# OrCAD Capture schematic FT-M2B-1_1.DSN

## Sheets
1 INDEX: title: 01-INDEX; rev: 1.1
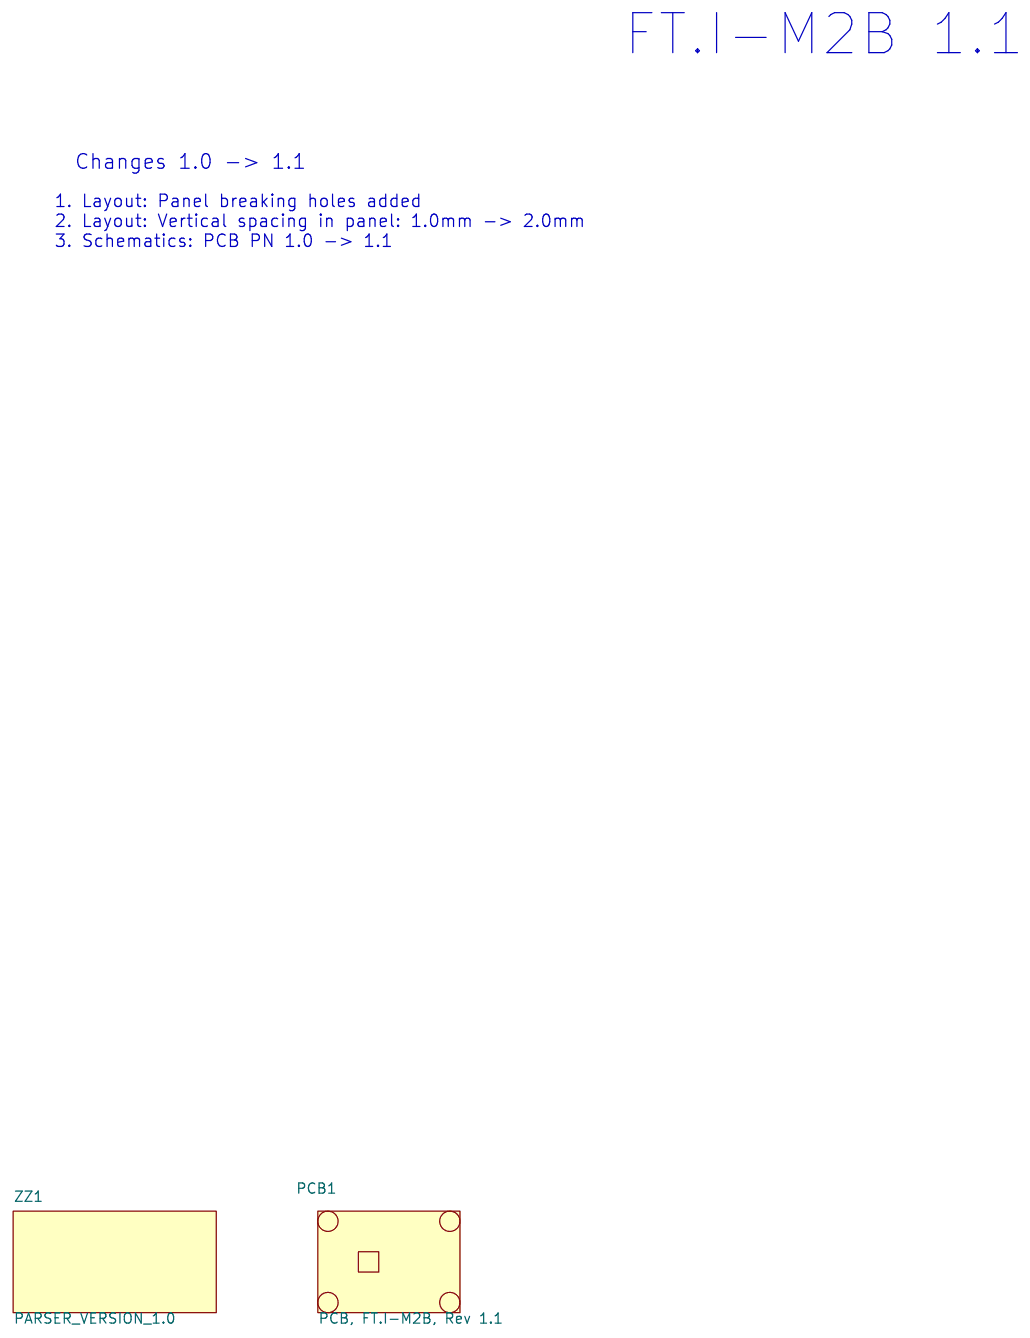
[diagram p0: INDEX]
2 TRIP: size A; title: 02-TRIP
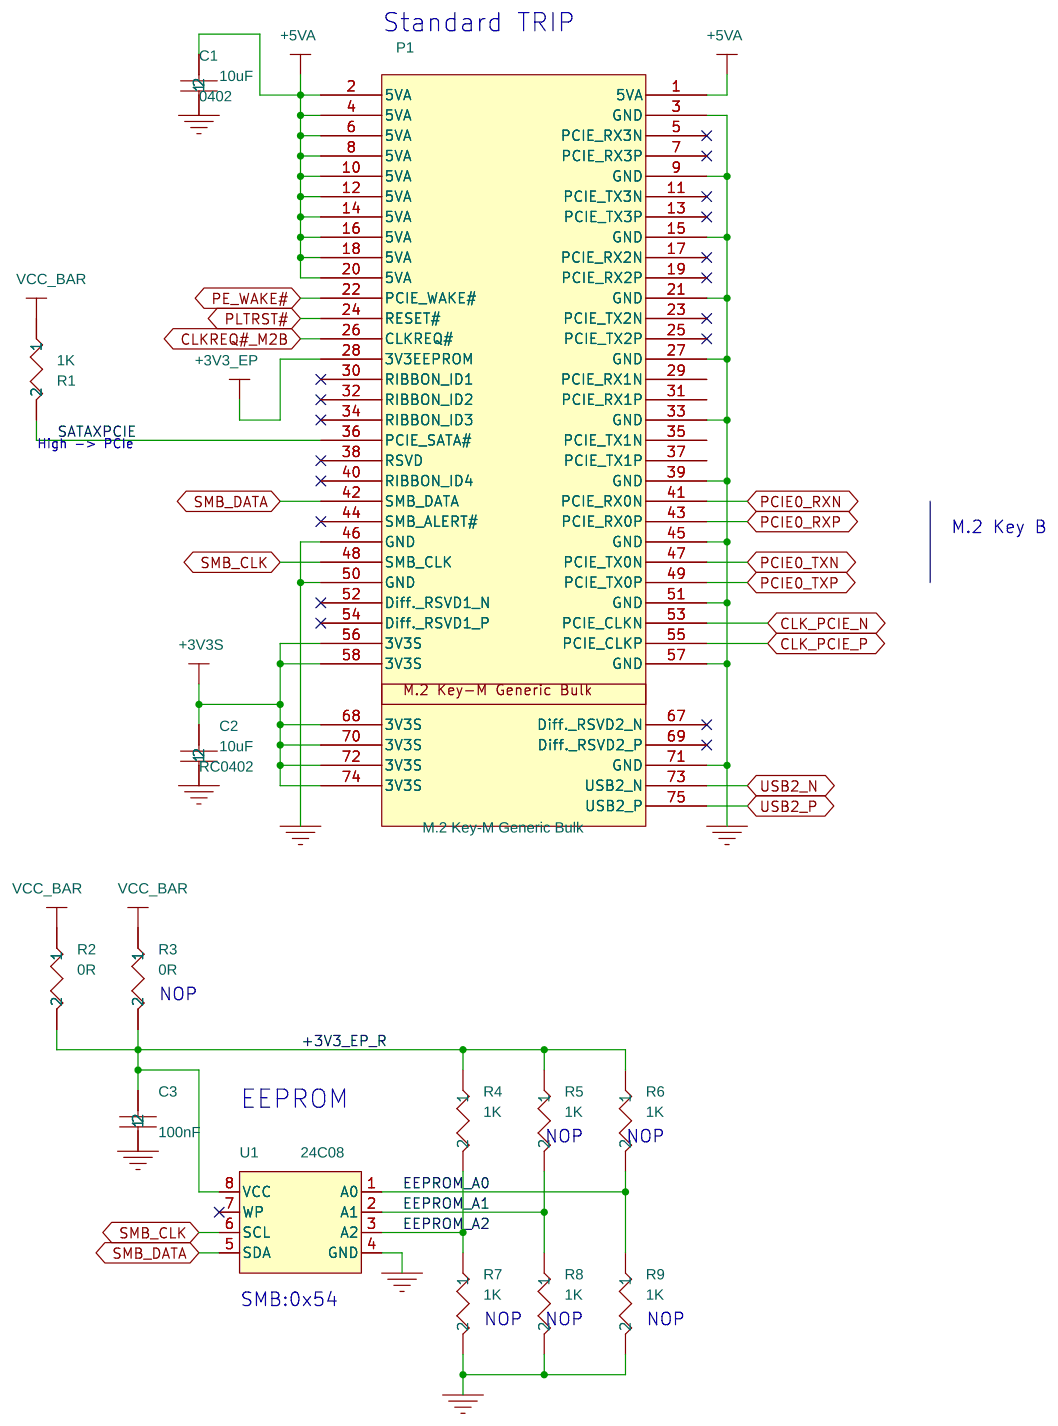
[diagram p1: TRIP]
3 M.2 Key B: size A4; title: 04-M.2 Key B
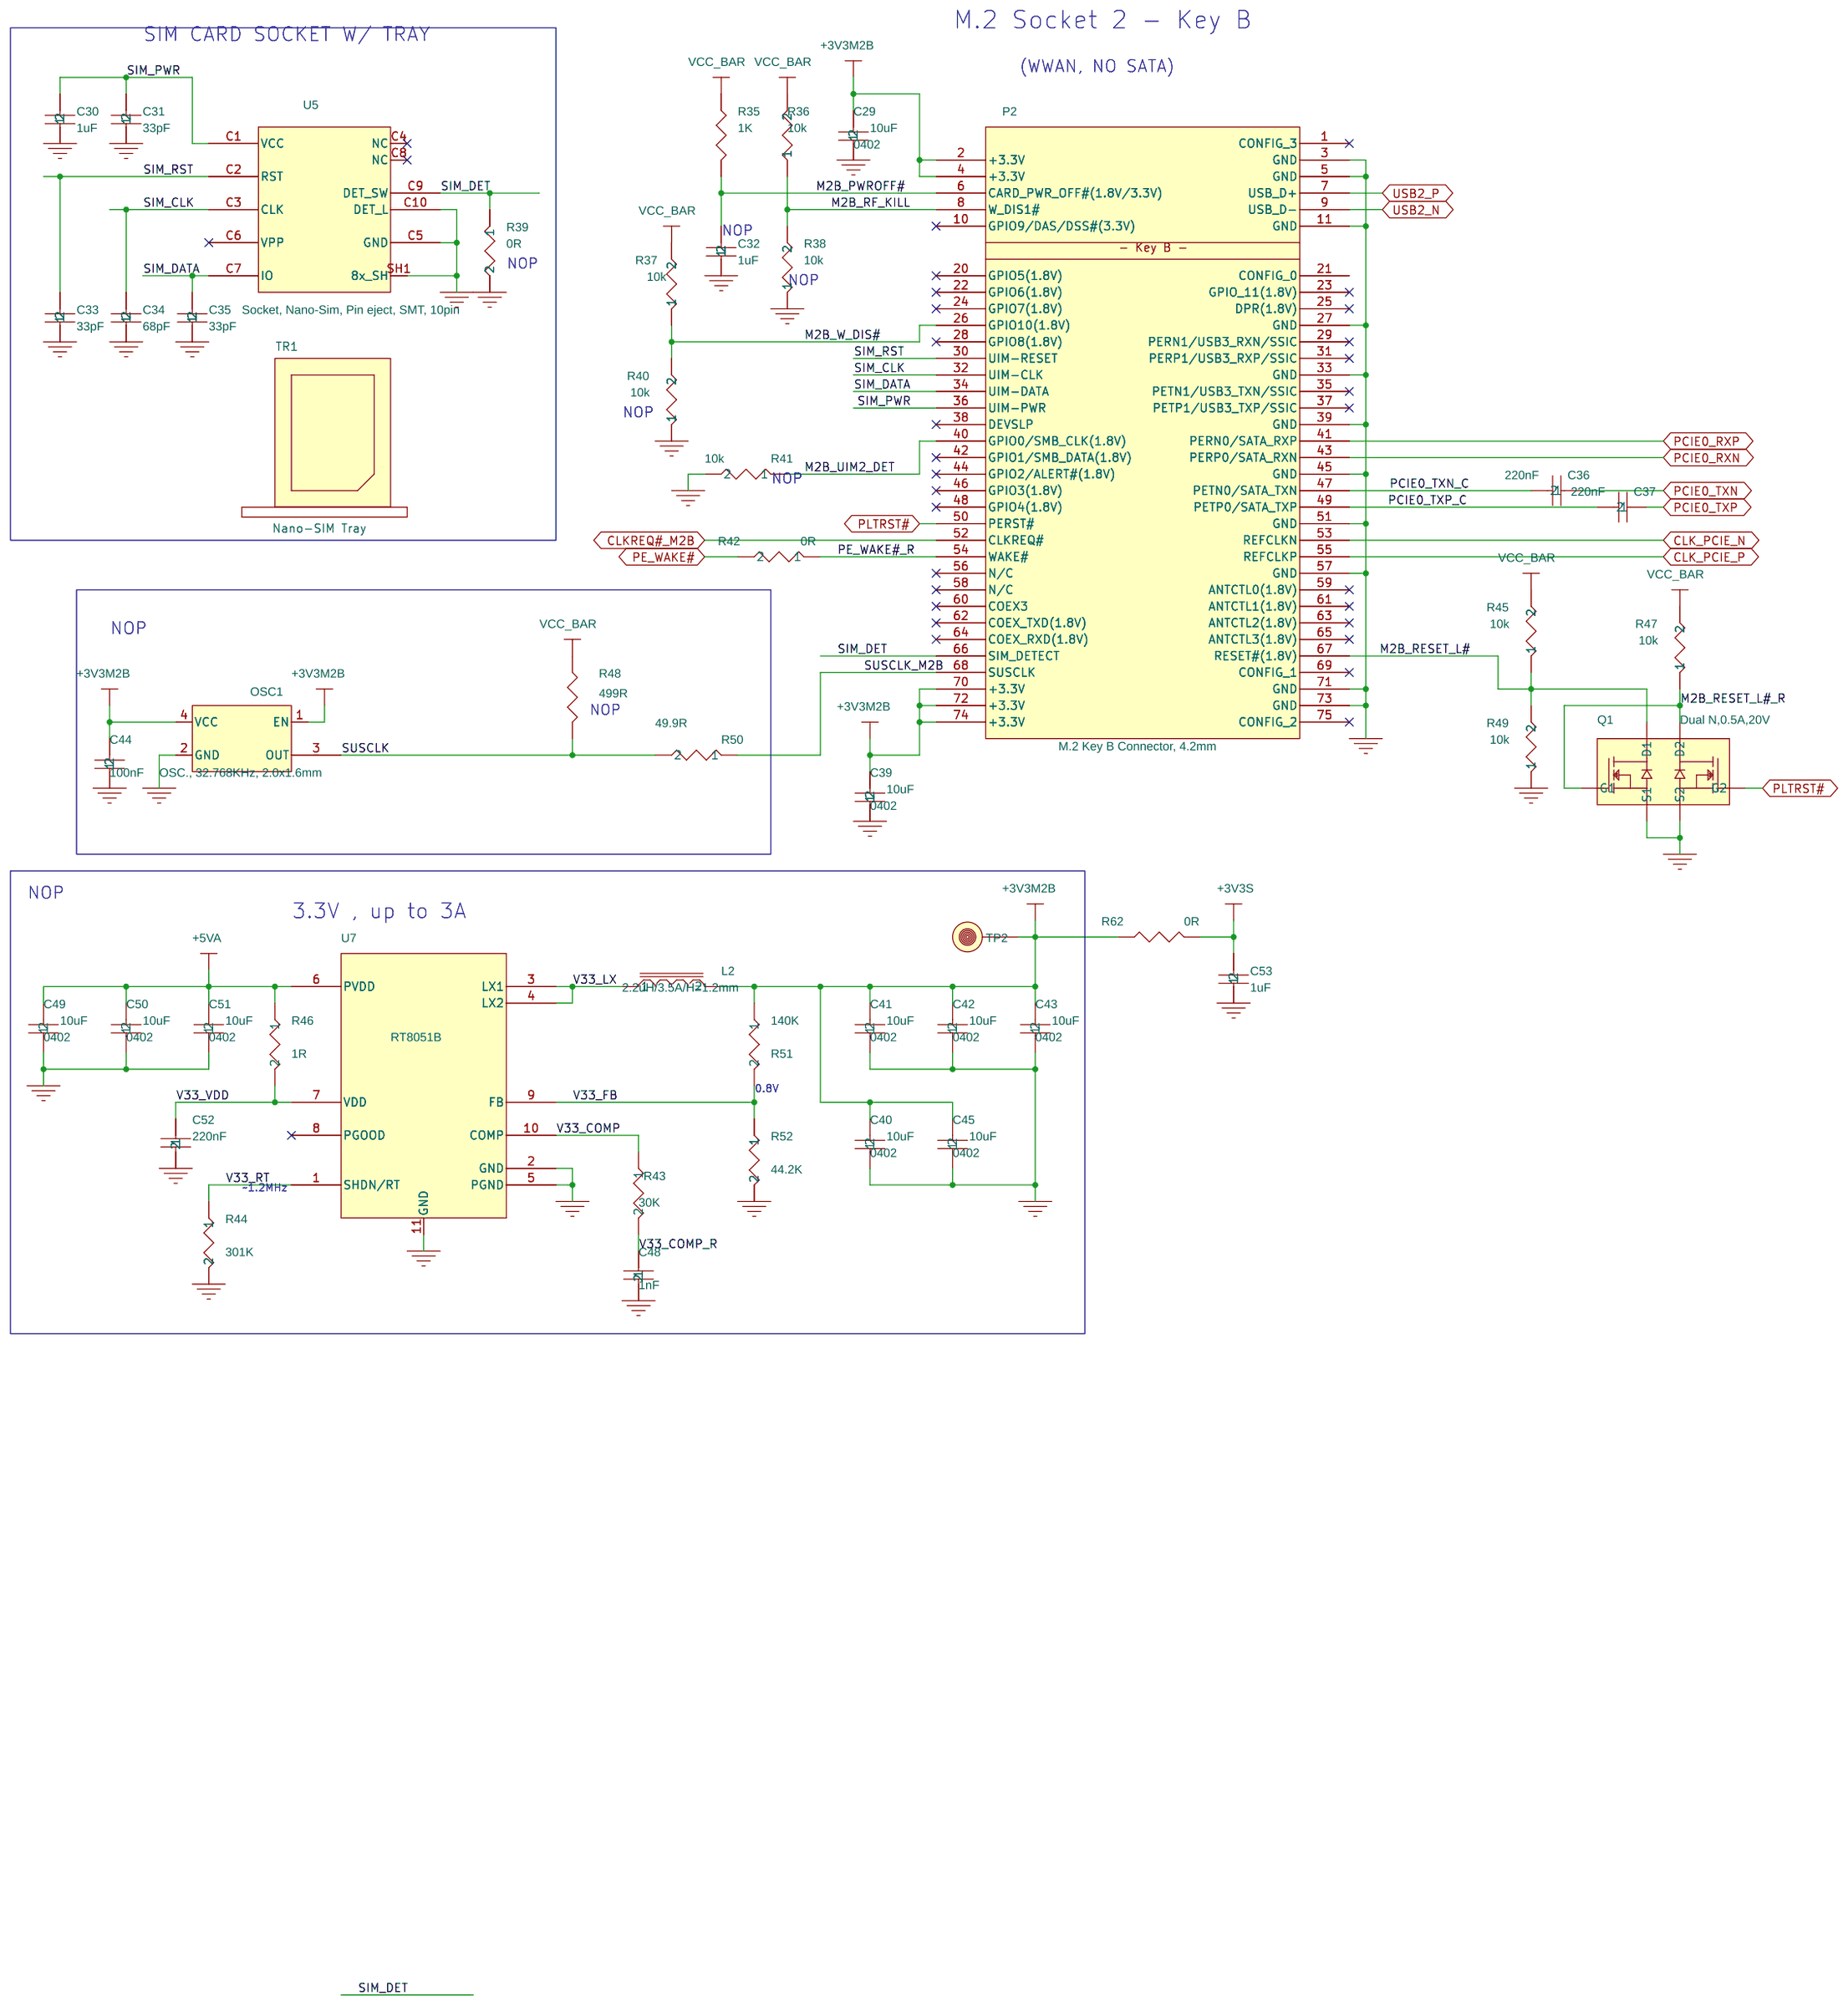
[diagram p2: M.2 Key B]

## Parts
sheet INDEX
PCB1  PCB, FT.I-M2B, Rev 1.1
ZZ1  PARSER_VERSION_1.0
sheet M.2 Key B
C29  10uF  [0402]
C30  1uF  [RC0402]
C31  33pF  [RC0402]
C32  1uF  [RC0402]
C33  33pF  [RC0402]
C34  68pF  [RC0402]
C35  33pF  [RC0402]
C36  220nF  [RC0402]
C37  220nF  [RC0402]
C39  10uF  [0402]
C40  10uF  [0402]
C41  10uF  [0402]
C42  10uF  [0402]
C43  10uF  [0402]
C44  100nF  [RC0402]
C45  10uF  [0402]
C48  1nF  [RC0402]
C49  10uF  [0402]
C50  10uF  [0402]
C51  10uF  [0402]
C52  220nF  [RC0402]
C53  1uF  [RC0402]
L2  2.2uH/3.5A/H=1.2mm  [IND4_3x4_7SM]
OSC1  OSC., 32.768KHz, 2.0x1.6mm  [OSC3225]
P2  M.2 Key B Connector, 4.2mm  [NGFF67P4HBkeySM]
Q1  Dual N,0.5A,20V  [SOT-563-6]
R35  1K  [RC0402]
R36  10k  [RC0402]
R37  10k  [RC0402]
R38  10k  [RC0402]
R39  0R  [RC0402]
R40  10k  [RC0402]
R41  10k  [RC0402]
R42  0R  [RC0402]
R43  30K  [RC0402]
R44  301K  [RC0402]
R45  10k  [RC0402]
R46  1R  [RC0402]
R47  10k  [RC0402]
R48  499R  [RC0402]
R49  10k  [RC0402]
R50  49.9R  [RC0402]
R51  140K  [RC0402]
R52  44.2K  [RC0402]
R62  0R  [RC0402]
TP2  TP
TR1  Nano-SIM Tray
U5  Socket, Nano-Sim, Pin eject, SMT, 10pin  [SKT-MicroSIM6-SM]
U7  RT8051B  [DFN3x3-10]
sheet TRIP
C1  10uF  [0402]
C2  10uF  [RC0402]
C3  100nF  [RC0402]
P1  M.2 Key-M Generic Bulk  [NGFF67P8HMkeySM]
R1  1K  [RC0402]
R2  0R  [RC0402]
R3  0R  [RC0402]
R4  1K  [RC0402]
R5  1K  [RC0402]
R6  1K  [RC0402]
R7  1K  [RC0402]
R8  1K  [RC0402]
R9  1K  [RC0402]
U1  24C08  [MO-229VCED-2]

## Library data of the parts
PCB1 = SBC-iHSW_Rev_1.0: CLABCONF0: FT.I-M2B; P/N: 188C03411U
ZZ1 = PARSER_VERSION_1.0: CLABCONF0: FT.I-M2B
C1 C29 = 100nF,_10V,_X7R,_10%,_0402: CLABCONF0: FT.I-M2B; P/N: 151B10600S
C30 = 15pF,_50V,_NPO,_5%,_0402_5: CLABCONF0: FT.I-M2B; P/N: 151C10500S
C31 = 15pF,_50V,_NPO,_5%,_0402_6: CLABCONF0: FT.I-M2B; P/N: 151K33000S
C32 = 15pF,_50V,_NPO,_5%,_0402_1: CLABCONF0: NOP; P/N: 151C10500S
C33 = 15pF,_50V,_NPO,_5%,_0402_3: CLABCONF0: FT.I-M2B; P/N: 151K33000S
C34 = 15pF,_50V,_NPO,_5%,_0402: CLABCONF0: FT.I-M2B; P/N: 155068R00S
C35 = 15pF,_50V,_NPO,_5%,_0402_4: CLABCONF0: FT.I-M2B; P/N: 151K33000S
C36 = 100nF,_10V,_X7R,_10%,_0402_3: CLABCONF0: FT.I-M2B; P/N: 151C22400S
C37 = 100nF,_10V,_X7R,_10%,_0402_2: CLABCONF0: FT.I-M2B; P/N: 151C22400S
C39 = 100nF,_10V,_X7R,_10%,_0402_13: CLABCONF0: FT.I-M2B; P/N: 151B10600S
C40 = 100nF,_10V,_X7R,_10%,_0402_4: CLABCONF0: NOP; P/N: 151B10600S
C41 = 100nF,_10V,_X7R,_10%,_0402_5: CLABCONF0: NOP; P/N: 151B10600S
C42 = 100nF,_10V,_X7R,_10%,_0402_6: CLABCONF0: NOP; P/N: 151B10600S
C43 = 100nF,_10V,_X7R,_10%,_0402_7: CLABCONF0: NOP; P/N: 151B10600S
C44 = 100nF,_10V,_X7R,_10%,_0402_10: CLABCONF0: NOP; P/N: 151B10400S
C45 = 100nF,_10V,_X7R,_10%,_0402_12: CLABCONF0: NOP; P/N: 151B10600S
C48 = 22nF,_10V,_X7R,_10%,_0402: CLABCONF0: NOP; P/N: 151D10200S
C49 = 100nF,_10V,_X7R,_10%,_0402_8: CLABCONF0: NOP; P/N: 151B10600S
C50 = 100nF,_10V,_X7R,_10%,_0402_9: CLABCONF0: NOP; P/N: 151B10600S
C51 = 100nF,_10V,_X7R,_10%,_0402_11: CLABCONF0: NOP; P/N: 151B10600S
C52 = 100nF,_10V,_X7R,_10%,_0402_1: CLABCONF0: NOP; P/N: 151C22400S
C53 = 15pF,_50V,_NPO,_5%,_0402_2: CLABCONF0: FT.I-M2B; P/N: 151C10500S
L2 = Ind,_2.2uH,_3A_5A,_58_mOhm: CLABCONF0: NOP; P/N: 147A2R206S
OSC1 = 25MHz,50PPM,OSC3225,_3.3V: CLABCONF0: FT.I-M2B; P/N: 141C32300I
P2 = M.2_Key_B_Connector: CLABCONF0: FT.I-M2B; P/N: 182K06702S
Q1 = DUAL_N-MOSFET,_0.5A_20V: CLABCONF0: FT.I-M2B
R35 = RESISTOR: CLABCONF0: FT.I-M2B; P/N: 161C10011S
R36 = 1M_,5%,_0402_6: CLABCONF0: FT.I-M2B; P/N: 161C10021S
R37 = 1M_,5%,_0402_1: CLABCONF0: FT.I-M2B; P/N: 161C10021S
R38 = 1M_,5%,_0402_3: CLABCONF0: NOP; P/N: 161C10021S
R39 = 0R: CLABCONF0: NOP
R40 = 1M_,5%,_0402_5: CLABCONF0: NOP; P/N: 161C10021S
R41 = 1M_,5%,_0402_2: CLABCONF0: NOP; P/N: 161C10021S
R42 = 0R_1: CLABCONF0: FT.I-M2B
R43 = 4.02K,1%,0402_3: CLABCONF0: NOP; P/N: 161C30021S
R44 = 4.02K,1%,0402: CLABCONF0: NOP; P/N: 161C30131S
R45 = 1M_,5%,_0402: CLABCONF0: FT.I-M2B; P/N: 161C10021S
R46 = 4.02K,1%,0402_2: CLABCONF0: NOP; P/N: 161C1R001S
R47 = 1M_,5%,_0402_4: CLABCONF0: FT.I-M2B; P/N: 161C10021S
R48 = RESISTOR: CLABCONF0: NOP; P/N: 161C49901S
R49 = 1M_,5%,_0402_7: CLABCONF0: FT.I-M2B; P/N: 161C10021S
R50 = 348R,1%,0402,1_16W: CLABCONF0: NOP; P/N: 161C49R91S
R51 = 4.02K,1%,0402_1: CLABCONF0: NOP; P/N: 161C14031S
R52 = 4.02K,1%,0402_4: CLABCONF0: NOP; P/N: 161C44221S
R62 = 10K,1%,0402,1_16W_0: CLABCONF0: FT.I-M2B; P/N: 161C00005S
TP2 = TP_SMT: CLABCONF0: NOP
TR1 = Nano-SIM_Tray: CLABCONF0: FT.I-M2B; P/N: 190Z00000
U5 = Nano-SIM_Socket_pin-eject: CLABCONF0: FT.I-M2B; P/N: 190I01000S
U7 = RT8051B_4: CLABCONF0: NOP; P/N: 123V5R004S
C2 = 100nF,_10V,_X7R,_10%,_0402_1: CLABCONF0: FT.I-M2B; P/N: 151B10600S
C3 = 15pF,_50V,_NPO,_5%,_0402: CLABCONF0: FT.I-M2B; P/N: 151B10400S
P1 = M.2_Key-M_Generic_Bulk: CLABCONF0: FT.I-M2B; P/N: 182K06700S
R1 = 348R,1%,0402,1_16W_5: CLABCONF0: FT.I-M2B; P/N: 161C10011S
R2 = 348R,1%,0402,1_16W_7: CLABCONF0: FT.I-M2B; P/N: 161C00005S
R3 = 348R,1%,0402,1_16W_6: CLABCONF0: NOP; P/N: 161C00005S
R4 = 348R,1%,0402,1_16W_1: CLABCONF0: FT.I-M2B; P/N: 161C10011S
R5 = 348R,1%,0402,1_16W_2: CLABCONF0: NOP; P/N: 161C10011S
R6 = 348R,1%,0402,1_16W: CLABCONF0: NOP; P/N: 161C10011S
R7 = 348R,1%,0402,1_16W_8: CLABCONF0: NOP; P/N: 161C10011S
R8 = 348R,1%,0402,1_16W_4: CLABCONF0: NOP; P/N: 161C10011S
R9 = 348R,1%,0402,1_16W_3: CLABCONF0: NOP; P/N: 161C10011S
U1 = 24C02,_serial_EE,_2KB,_I2C: CLABCONF0: FT.I-M2B; P/N: 111S31000S

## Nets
+3V3_EP: P1.28(3V3EEPROM) R2.1
+3V3_EP_R: C3.2 R2.2 R3.2 R4.1 R5.1 R6.1 U1.8(VCC)
+3V3M2B: C29.2 C39.2 C40.2 C41.2 C42.2 C43.2 C44.2 C45.2 L2.2 OSC1.1(EN) OSC1.4(VCC) P2.2(+3.3V) P2.4(+3.3V) P2.70(+3.3V) P2.72(+3.3V) P2.74(+3.3V) R35.1 R36.2 R37.2 R45.2 R47.2 R48.1 R51.1 R62.1 TP2.1
+3V3S: C2.2 C53.2 P1.56(3V3S) P1.58(3V3S) P1.68(3V3S) P1.70(3V3S) P1.72(3V3S) P1.74(3V3S) R1.1 R3.1 R62.2
+5VA: C1.2 C49.2 C50.2 C51.2 P1.1(5VA) P1.2(5VA) P1.4(5VA) P1.6(5VA) P1.8(5VA) P1.10(5VA) P1.12(5VA) P1.14(5VA) P1.16(5VA) P1.18(5VA) P1.20(5VA) R46.1 U7.6(PVDD)
GND: C1.1 C2.1 C3.1 C29.1 C30.1 C31.1 C32.1 C33.1 C34.1 C35.1 C39.1 C40.1 C41.1 C42.1 C43.1 C44.1 C45.1 C48.2 C49.1 C50.1 C51.1 C52.2 C53.1 OSC1.2(GND) P1.3(GND) P1.9(GND) P1.15(GND) P1.21(GND) P1.27(GND) P1.33(GND) P1.39(GND) P1.45(GND) P1.46(GND) P1.50(GND) P1.51(GND) P1.57(GND) P1.71(GND) P2.3(GND) P2.5(GND) P2.11(GND) P2.27(GND) P2.33(GND) P2.39(GND) P2.45(GND) P2.51(GND) P2.57(GND) P2.71(GND) P2.73(GND) Q1.1(S1) Q1.4(S2) R7.2 R8.2 R9.2 R38.1 R39.2 R40.1 R41.2 R44.2 R49.1 R52.2 U1.4(GND) U5.C5(GND) U5.C10(DET_L) U5.SH1(8x_SH) U7.2(GND) U7.5(PGND) U7.11(GND)
V33_COMP: R43.1 U7.10(COMP)
V33_COMP_R: C48.1 R43.2
V33_FB: R51.2 R52.1 U7.9(FB)
V33_LX: L2.1 U7.3(LX1) U7.4(LX2)
V33_RT: R44.1 U7.1(SHDN/RT)
V33_VDD: C52.1 R46.2 U7.7(VDD)
CLK_PCIE_N: P1.53(PCIE_CLKN) P2.53(REFCLKN)
CLK_PCIE_P: P1.55(PCIE_CLKP) P2.55(REFCLKP)
CLKREQ#_M2B: P1.26(CLKREQ#) P2.52(CLKREQ#)
EEPROM_A0: R6.2 R9.1 U1.1(A0)
EEPROM_A1: R5.2 R8.1 U1.2(A1)
EEPROM_A2: R4.2 R7.1 U1.3(A2)
M2B_PWROFF#: C32.2 P2.6(CARD_PWR_OFF#(1.8V/3.3V)) R35.2
M2B_RESET_L#: P2.67(RESET#(1.8V)) Q1.6(D1) R45.1 R49.2
M2B_RESET_L#_R: Q1.2(G1) Q1.3(D2) R47.1
M2B_RF_KILL: P2.8(W_DIS1#) R36.1 R38.2
M2B_UIM2_DET: P2.40(GPIO0/SMB_CLK(1.8V)) R41.1
M2B_W_DIS#: P2.26(GPIO10(1.8V)) R37.1 R40.2
PCIE0_RXN: P1.41(PCIE_RX0N) P2.43(PERP0/SATA_RXN)
PCIE0_RXP: P1.43(PCIE_RX0P) P2.41(PERN0/SATA_RXP)
PCIE0_TXN: C36.1 P1.47(PCIE_TX0N)
PCIE0_TXN_C: C36.2 P2.47(PETN0/SATA_TXN)
PCIE0_TXP: C37.1 P1.49(PCIE_TX0P)
PCIE0_TXP_C: C37.2 P2.49(PETP0/SATA_TXP)
PE_WAKE#: P1.22(PCIE_WAKE#) R42.2
PE_WAKE#_R: P2.54(WAKE#) R42.1
PLTRST#: P1.24(RESET#) P2.50(PERST#) Q1.5(G2)
SATAXPCIE: P1.36(PCIE_SATA#) R1.2
SIM_CLK: C34.2 P2.32(UIM-CLK) U5.C3(CLK)
SIM_DATA: C35.2 P2.34(UIM-DATA) U5.C7(IO)
SIM_DET: P2.66(SIM_DETECT) R39.1 U5.C9(DET_SW)
SIM_PWR: C30.2 C31.2 P2.36(UIM-PWR) U5.C1(VCC)
SIM_RST: C33.2 P2.30(UIM-RESET) U5.C2(RST)
SMB_CLK: P1.48(SMB_CLK) U1.6(SCL)
SMB_DATA: P1.42(SMB_DATA) U1.5(SDA)
SUSCLK: OSC1.3(OUT) R48.2 R50.2
SUSCLK_M2B: P2.68(SUSCLK) R50.1
USB2_N: P1.73(USB2_N) P2.9(USB_D-)
USB2_P: P1.75(USB2_P) P2.7(USB_D+)

Not connected (* = marked no-connect by the designer): P1 5(PCIE_RX3N)* 7(PCIE_RX3P)* 11(PCIE_TX3N)* 13(PCIE_TX3P)* 17(PCIE_RX2N)* 19(PCIE_RX2P)* 23(PCIE_TX2N)* 25(PCIE_TX2P)* 29(PCIE_RX1N) 30(RIBBON_ID1)* 31(PCIE_RX1P) 32(RIBBON_ID2)* 34(RIBBON_ID3)* 35(PCIE_TX1N) 37(PCIE_TX1P) 38(RSVD)* 40(RIBBON_ID4)* 44(SMB_ALERT#)* 52(Diff._RSVD1_N)* 54(Diff._RSVD1_P)* 67(Diff._RSVD2_N)* 69(Diff._RSVD2_P)*; P2 1(CONFIG_3)* 10(GPIO9/DAS/DSS#(3.3V))* 20(GPIO5(1.8V))* 21(CONFIG_0) 22(GPIO6(1.8V))* 23(GPIO_11(1.8V))* 24(GPIO7(1.8V))* 25(DPR(1.8V))* 28(GPIO8(1.8V))* 29(PERN1/USB3_RXN/SSIC)* 31(PERP1/USB3_RXP/SSIC)* 35(PETN1/USB3_TXN/SSIC)* 37(PETP1/USB3_TXP/SSIC)* 38(DEVSLP)* 42(GPIO1/SMB_DATA(1.8V))* 44(GPIO2/ALERT#(1.8V))* 46(GPIO3(1.8V))* 48(GPIO4(1.8V))* 56(N/C)* 58(N/C)* 59(ANTCTL0(1.8V))* 60(COEX3)* 61(ANTCTL1(1.8V))* 62(COEX_TXD(1.8V))* 63(ANTCTL2(1.8V))* 64(COEX_RXD(1.8V))* 65(ANTCTL3(1.8V))* 69(CONFIG_1)* 75(CONFIG_2)*; U1 7(WP)*; U5 C4(NC)* C6(VPP)* C8(NC)*; U7 8(PGOOD)*

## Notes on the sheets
sheet 1
- FT.I-M2B 1.1
- Changes 1.0 -> 1.1
- 1. Layout: Panel breaking holes added
  2. Layout: Vertical spacing in panel: 1.0mm -> 2.0mm
  3. Schematics: PCB PN 1.0 -> 1.1
sheet 2
- Standard TRIP
- High -> PCIe
- M.2 Key B
- NOP
- EEPROM
- NOP
- NOP
- SMB:0x54
- NOP
- NOP
- NOP
sheet 3
- M.2 Socket 2 - Key B
- SIM CARD SOCKET W/ TRAY
- (WWAN, NO SATA)
- NOP
- NOP
- NOP
- NOP
- NOP
- NOP
- NOP
- NOP
- 3.3V , up to 3A
- 0.8V
- ~1.2MHz
